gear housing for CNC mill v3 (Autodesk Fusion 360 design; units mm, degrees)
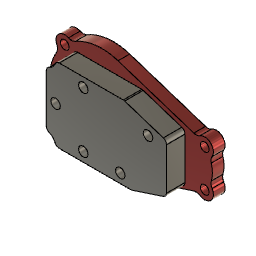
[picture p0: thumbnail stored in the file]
description: Gear Housing Assembly
derived_base_feature "Derived Base Feature1"
derived_base_feature "Derived Base Feature1" bodies "Front Housing"
derived_base_feature "Derived Base Feature1" bodies "Front Cover"
derived_base_feature "Derived Base Feature1" bodies "Back Housing"
as_built_joint "As-built1"
offset_faces "OffsetFaces1" distance 5
delete_face "DeleteFace1"
delete_face "DeleteFace2"
sketch "Sketch1" plane through (0, -21, 0) normal (0, -1, 0) x axis (1, 0, 0)
  line L1 (11.1724, 34.2225) -> (63.2283, 17.2281)
  line L2 (63.2283, -17.2281) -> (11.1724, -34.2225)
  arc A1 centre (64.7801, 21.9812) radius 5 clockwise from (67.4836, 17.7752) to (63.2283, 17.2281)
  arc A2 centre (0, 0) radius 36 clockwise from (-18.189, 31.067) to (11.1724, 34.2225)
  arc A3 centre (-20.7152, 35.3819) radius 5 clockwise from (-18.189, 31.067) to (-22.8701, 30.8701)
  arc A4 centre (-25.4558, 25.4558) radius 6 clockwise from (-30.8701, 22.8701) to (-22.8701, 30.8701)
  arc A5 centre (-35.3819, 20.7152) radius 5 clockwise from (-30.8701, 22.8701) to (-31.067, 18.189)
  arc A6 centre (0, 0) radius 36 clockwise from (-31.067, -18.189) to (-31.067, 18.189)
  arc A7 centre (-35.3819, -20.7152) radius 5 clockwise from (-31.067, -18.189) to (-30.8701, -22.8701)
  arc A8 centre (-25.4558, -25.4558) radius 6 clockwise from (-22.8701, -30.8701) to (-30.8701, -22.8701)
  arc A9 centre (-20.7152, -35.3819) radius 5 clockwise from (-22.8701, -30.8701) to (-18.189, -31.067)
  arc A10 centre (0, 0) radius 36 clockwise from (11.1724, -34.2225) to (-18.189, -31.067)
  arc A11 centre (64.7801, -21.9812) radius 5 clockwise from (63.2283, -17.2281) to (67.4836, -17.7752)
  arc A12 centre (70.7279, -12.7279) radius 6 clockwise from (75.774, -9.4818) to (67.4836, -17.7752)
  arc A13 centre (79.979, -6.7767) radius 5 clockwise from (75.774, -9.4818) to (75.201, -5.3035)
  arc A14 centre (58, 0) radius 18 clockwise from (75.201, 5.3035) to (75.201, -5.3035)
  arc A15 centre (79.979, 6.7767) radius 5 clockwise from (75.201, 5.3035) to (75.774, 9.4818)
  arc A16 centre (70.7279, 12.7279) radius 6 clockwise from (67.4836, 17.7752) to (75.774, 9.4818)
  circle C1 centre (70.7279, -12.7279) radius 3
  circle C2 centre (70.7279, 12.7279) radius 3
  circle C3 centre (-25.4558, -25.4558) radius 3
  circle C4 centre (-25.4558, 25.4558) radius 3
  circle C5 centre (0, 0) radius 5.25
  circle C6 centre (0, 0) radius 19.05
  point P1 (0, 0)
  point P34 (0, 0)
  point P35 (0, -19.05)
  point P36 (-19.05, 0)
  point P37 (0, 19.05)
  point P38 (44.45, 12.7)
  point P39 (25.4, -19.05)
  coincident P1 P34
  coincident C6 P35
  coincident C6 P36
  coincident C6 P37
  vertical P34 P35
  horizontal P1 P36
  vertical P1 P37
  dimension "d2" diameter C6 = 38.1
  dimension "d3" distance P1 P38 = 44.45
  dimension "d4" distance P1 P38 = 12.7
  dimension "d5" distance P34 P39 = 25.4
  dimension "d6" distance P34 P39 = 19.05
hole "Hole1" HoleDepth 5.715 HoleDiameter 5.1308 TipAngle 118
ground "Ground1"
ground "Ground2"
ground "Ground3"
ground "Ground4"
position "Position1"
sketch "Sketch1" plane through (0, 0, 0) normal (0, 1, 0) x axis (1, 0, 0)
  line L1 (57.15, -25.4) -> (-25.4, -25.4)
  line L2 (57.15, 25.4) -> (57.15, -25.4)
  line L3 (-25.4, 25.4) -> (57.15, 25.4)
  line L4 (-25.4, -25.4) -> (-25.4, 25.4)
  line L5 (11.1724, -34.2225) -> (63.2283, -17.2281)
  line L6 (63.2283, 17.2281) -> (11.1724, 34.2225)
  line L7 (10.1871, -31.2042) -> (62.243, -14.2098)
  line L8 (62.7357, 15.719) -> (10.6797, 32.7134)
  circle C1 centre (-25.4558, -25.4558) radius 3
  circle C2 centre (-25.4558, 25.4558) radius 3
  circle C3 centre (-25.4558, -25.4558) radius 6.35
  circle C4 centre (-25.4558, 25.4558) radius 6.35
  point P1 (0, 0)
  horizontal L1
  vertical L2
  horizontal L3
  vertical L4
  concentric C1 C3
  concentric C2 C4
  equal C3 C4
  dimension "d10" distance P1 L1 = 25.4
  dimension "d11" distance P1 L3 = 25.4 (= "d10")
  dimension "d12" distance P1 L2 = 57.15
  dimension "d13" distance P1 L4 = 25.4
  dimension "d14" diameter C3 = 12.7
  dimension "d15" = 3.175
  dimension "d16" = 1.5875
extrude "Extrude1" new body sketch "Sketch1" profile of L1 L2 L3 L4 C3 C4 L7 L8 against normal blind 12.7
fillet "Fillet1" radius 3.175
hole "Hole1" HoleDepth 12.7 HoleDiameter 6.477 TipAngle 118
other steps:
thread "Thread1"
create_component "CreateComponent1"
create_component "CreateComponent5"
create_component "CreateComponent1"
create_component "CreateComponent2"
create_component "CreateComponent3"
named bodies: "Back Housing", "Front Cover", "Front Housing"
